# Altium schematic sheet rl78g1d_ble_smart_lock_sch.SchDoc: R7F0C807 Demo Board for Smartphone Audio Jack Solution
size A4; Date: 2014/4/20; Author: Renesas Electronics Corporation; Rev: V1.00; Number: R20UT0784EG0100; Company: Renesas Electronics (China) Co.,Ltd
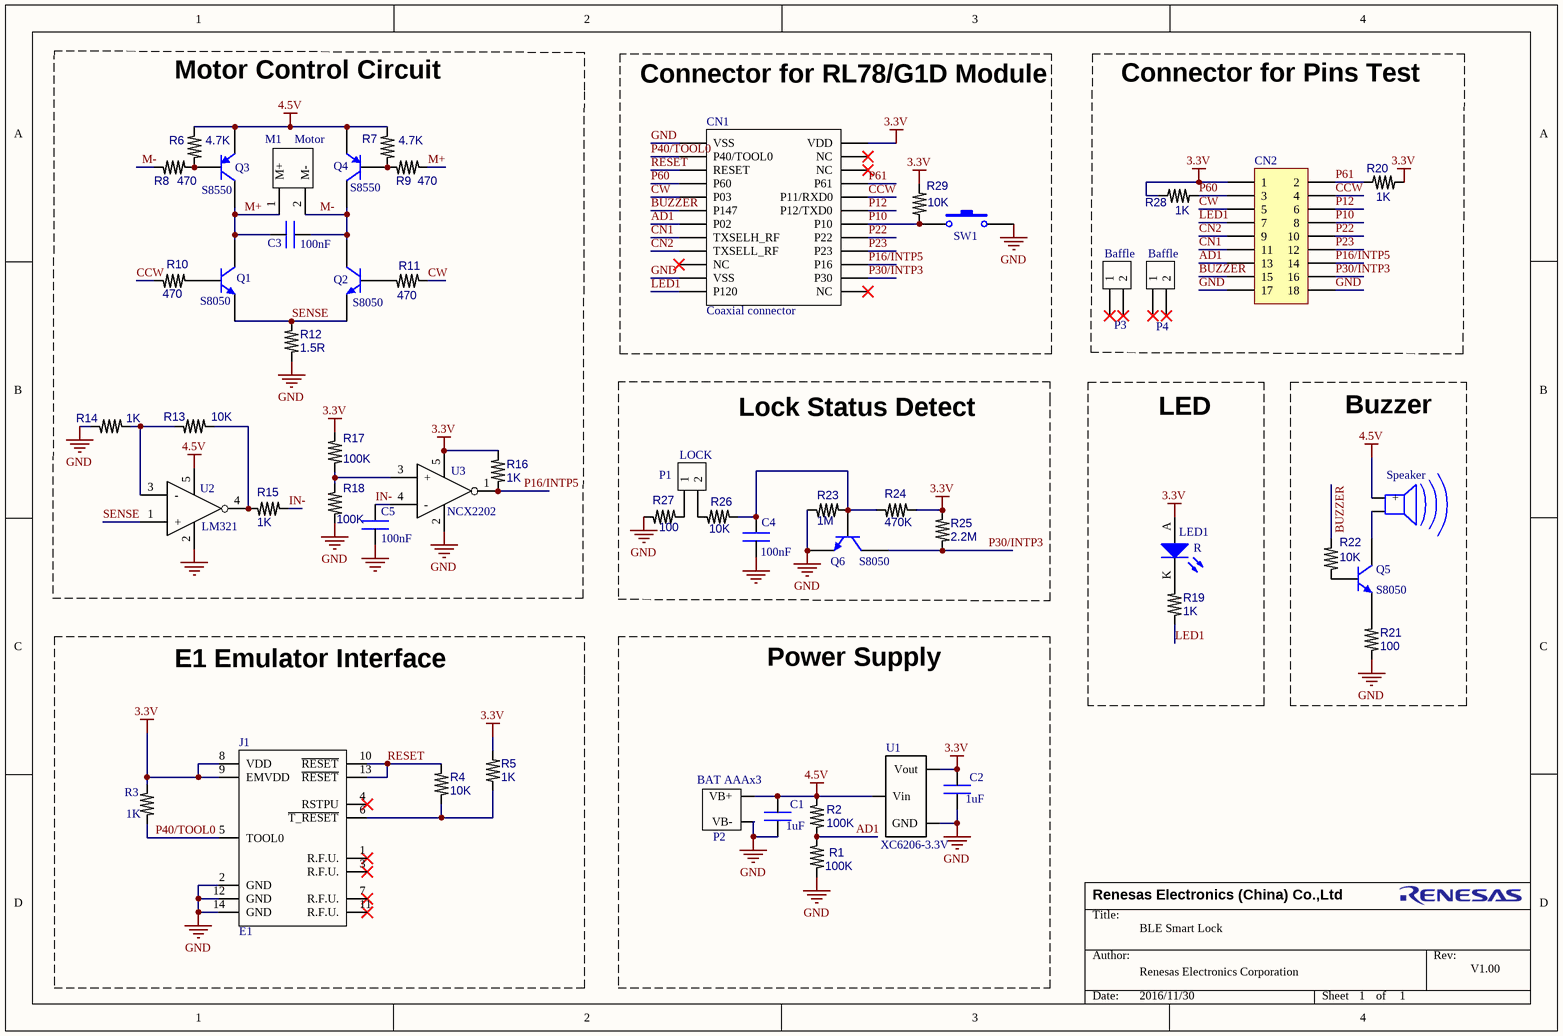
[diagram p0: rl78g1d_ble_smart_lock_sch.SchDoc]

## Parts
C1  1uF  [0603]
C2  1uF  [0603]
C3  100nF  [0603]
C4  100nF  [0603]
C5  100nF  [0603]
CN1  Coaxial connector  [CRS5001 - 24]
CN2  Header 9X2  [HDR2X9]  (value not drawn)
E1  J1  [E8 Connect - duplicate]
LED1  R  [LED 0603]
M1  Motor  [CON-2 D]
P1  LOCK  [HDR1X2]
P2  BAT AAAx3  [CON-2 D]
P3  Baffle  [HDR1X2]
P4  Baffle  [HDR1X2]
Q1  S8050  [SOT23A]
Q2  S8050  [SOT23A]
Q3  S8550  [SOT23A]
Q4  S8550  [SOT23A]
Q5  S8050  [SOT23A]
Q6  S8050  [SOT23A]
R1  100K  [0603]
R2  100K  [0603]
R3  1K  [0603]
R4  10K  [0603]
R5  1K  [0603]
R6  4.7K  [0603]
R7  4.7K  [0603]
R8  470  [0603]
R9  470  [0603]
R10  470  [0603]
R11  470  [0603]
R12  1.5R  [2512]
R13  10K  [0603]
R14  1K  [0603]
R15  1K  [0603]
R16  1K  [0603]
R17  100K  [0603]
R18  100K  [0603]
R19  1K  [0603]
R20  1K  [0603]
R21  100  [0603]
R22  10K  [0603]
R23  1M  [0603]
R24  470K  [0603]
R25  2.2M  [0603]
R26  10K  [0603]
R27  100  [0603]
R28  1K  [0603]
R29  10K  [0805]
Speaker  Buzzer  [BUZZER A]  (value not drawn)
SW1  SW-PB  [KEY B (6 X 6)]  (value not drawn)
U1  XC6206-3.3V  [SOT23A]
U2  LM321  [SOT-23-5]
U3  NCX2202  [SC-70 5]

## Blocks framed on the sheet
Motor Control Circuit: C3 C5 M1 Q1-Q4 R6-R18 U2 U3
Connector for RL78/G1D Module: CN1 R29 SW1
Connector for Pins Test: CN2 P3 P4 R20 R28
Lock Status Detect: C4 P1 Q6 R23-R27
LED: LED1 R19
Buzzer: Q5 R21 R22 Speaker
E1 Emulator Interface: E1 R3-R5
Power Supply: C1 C2 P2 R1 R2 U1

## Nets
3.3V: C2.1 CN1.2(VDD) CN2.1 E1.8(VDD) E1.9(EMVDD) LED1.A R3.1 R5.2 R16.2 R17.1 R20.1 R24.1 R25.1 R28.2 R29.1 U1.2(Vout) U3.5(+)
4.5V: C1.1 P2.1(VB+) Q3.2(E) Q4.2(E) R2.1 R6.2 R7.2 Speaker.1(+) U1.3(Vin) U2.5(+)
GND: C1.2 C2.2 C4.1 C5.1 CN1.1(VSS) CN1.21(VSS) CN2.17 CN2.18 E1.2(GND) E1.12(GND) E1.14(GND) P2.2(VB-) Q6.2(E) R1.2 R12.1 R14.1 R18.2 R21.1 R23.2 R27.2 SW1.1 U1.1(GND) U2.2(-) U3.2(-)
AD1: CN1.13(P02) CN2.13 R1.1 R2.2
BUZZER: CN1.11(P147) CN2.15 R22.2
CCW: CN1.10(P11/RXD0) CN2.4 R10.1
CN1: CN1.15(TXSELH_RF) CN2.11
CN2: CN1.17(TXSELL_RF) CN2.9
CW: CN1.9(P03) CN2.5 R11.2
IN-: C5.2 R15.2 U3.4(-)
LED1: CN1.23(P120) CN2.7 R19.2
M+: C3.1 M1.1(M+) Q1.3(C) Q3.3(C) R9.2
M-: C3.2 M1.2(M-) Q2.3(C) Q4.3(C) R8.1
P10: CN1.14(P10) CN2.8 R29.2 SW1.2
P12: CN1.12(P12/TXD0) CN2.6
P16/INTP5: CN1.20(P16) CN2.14 R16.1 U3.1(OUT_1)
P22: CN1.16(P22) CN2.10
P23: CN1.18(P23) CN2.12
P30/INTP3: CN1.22(P30) CN2.16 Q6.3(C) R25.2
P40/TOOL0: CN1.3(P40/TOOL0) E1.5(TOOL0) R3.2
P60: CN1.7(P60) CN2.3 R28.1
P61: CN1.8(P61) CN2.2 R20.2
RESET: CN1.5(RESET) E1.10(~{RESET}) E1.13(~{RESET}) R4.1
SENSE: Q1.2(E) Q2.2(E) R12.2 U2.1(+)
NetC4_2: C4.2 Q6.1(B) R23.1 R24.2 R26.1
NetE1_6: E1.6(~{T_RESET}) R4.2 R5.1
NetLED1_K: LED1.K R19.1
NetP1_1: P1.1 R27.1
NetP1_2: P1.2 R26.2
NetQ1_1: Q1.1(B) R10.2
NetQ2_1: Q2.1(B) R11.1
NetQ3_1: Q3.1(B) R6.1 R8.2
NetQ4_1: Q4.1(B) R7.1 R9.1
NetQ5_1: Q5.1(B) R22.1
NetQ5_2: Q5.2(E) R21.2
NetQ5_3: Q5.3(C) Speaker.2
NetR13_1: R13.1 R14.2 U2.3(-)
NetR13_2: R13.2 R15.1 U2.4(OUT_1)
NetR17_2: R17.2 R18.1 U3.3(+)

Not connected (* = marked no-connect by the designer): CN1 4(NC)* 6(NC)* 19(NC)* 24(NC)*; E1 1(R.F.U.)* 3(R.F.U.)* 4(RSTPU)* 7(R.F.U.)* 11(R.F.U.)*; P3 1* 2*; P4 1* 2*

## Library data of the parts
C1-C5 = CAP
CN2 = Header 9X2: Header, 9-Pin, Dual row
E1 = E1
LED1 = LED2: Typical RED, GREEN, YELLOW, AMBER GaAs LED
P1 P3 P4 = Header-2: Header, 4-Pin
P2 = Cell Battery: Header, 4-Pin
Q1 Q2 Q5 Q6 = NPN
Q3 Q4 = PNP
R1-R29 = RES
Speaker = SPEAKER
SW1 = SW-PB: Switch
U1 = XC6206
